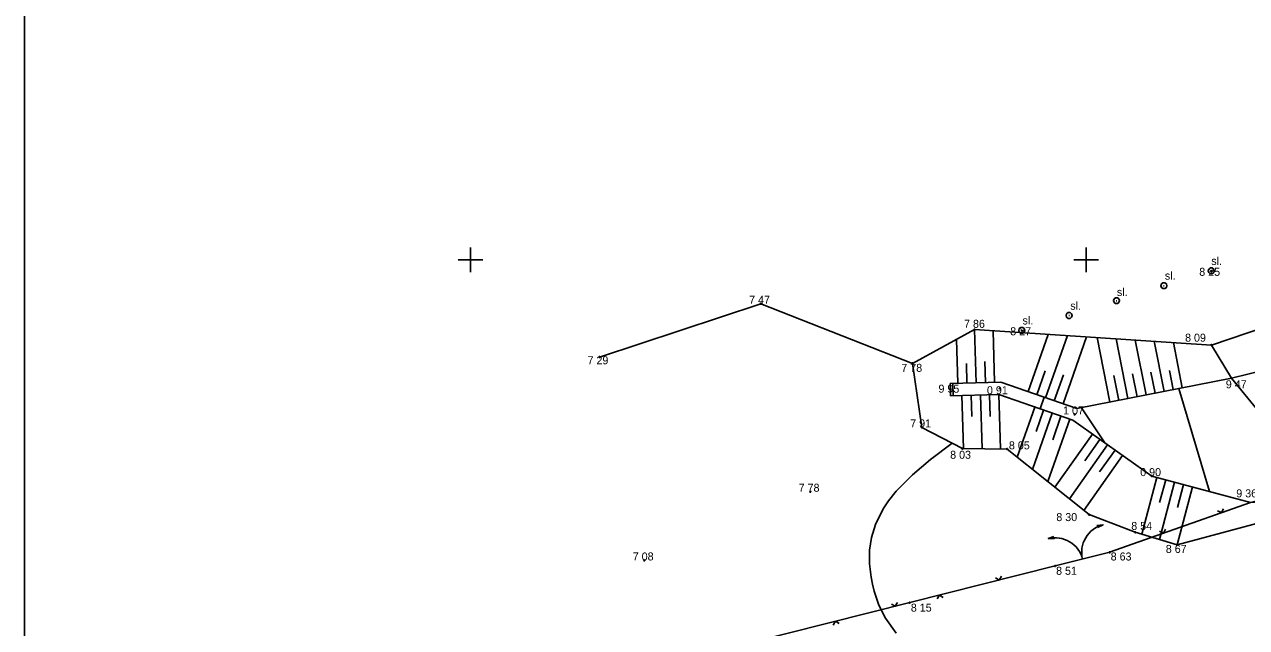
# Model space of a CAD drawing. Extents: x -684336 to -684039, y -993109 to -992688.
# Drawn here: x -684336.2 to -684237, y -992829.9 to -992780.9 of the extents above; entities that cross this region are included whole.
import ezdxf

# ---------------------------------------------------------------- set-up
doc = ezdxf.new("R2010")
doc.units = 0
for name, color, linetype in [('51', 7, 'Continuous'), ('53', 7, 'Continuous'), ('55', 7, 'Continuous'), ('56', 7, 'Continuous'), ('57', 7, 'Continuous'), ('60', 7, 'Continuous'), ('70', 7, 'Continuous'), ('81', 7, 'Continuous')]:
    doc.layers.add(name, color=color, linetype=linetype)

msp = doc.modelspace()

# ---------------------------------------------------------------- linework, layer by layer
at = {"layer": '51'}
for points in [[(-684155.696, -992787.999), (-684158.08, -992789.98), (-684161.21, -992793.24), (-684163.83, -992796.06), (-684166.91, -992797.89), (-684183.05, -992802.89), (-684200, -992808.38), (-684218.61, -992814.31), (-684231.09, -992818.35), (-684236.66, -992819.71), (-684248.11, -992823.77)], [(-684161.21, -992793.24), (-684163.51, -992789.57), (-684179.03, -992792.54), (-684203.02, -992799.48), (-684222.3, -992805.72), (-684238.2, -992809.62), (-684250.775, -992812.098)], [(-684251.105, -992813.042), (-684244.68, -992817.58), (-684236.66, -992819.71), (-684231.37, -992819.36), (-684210.59, -992812.91), (-684194.44, -992808.31), (-684190.16, -992807.38), (-684180.44, -992804.41), (-684173.82, -992803.72), (-684160.95, -992797.464)], [(-684216.49, -992799), (-684239.84, -992806.93), (-684259.07, -992805.67), (-684264.11, -992808.42), (-684263.35, -992813.62), (-684260.06, -992815.34), (-684256.43, -992815.38), (-684249.77, -992820.71), (-684246.02, -992822.14), (-684242.63, -992823.16), (-684230.34, -992819.85)], [(-684250.775, -992812.098), (-684256.942, -992809.937), (-684261.055, -992810.06)], [(-684261.025, -992811.06), (-684261.055, -992810.06)], [(-684251.105, -992813.042), (-684257.098, -992810.943), (-684261.025, -992811.06)], [(-684238.864, -992820.226), (-684239.016, -992820.545), (-684239.335, -992820.393)], [(-684243.577, -992821.897), (-684243.729, -992822.216), (-684244.048, -992822.064)], [(-684227.21, -992890.21), (-684237.13, -992893.77), (-684248.6, -992898.04), (-684263.09, -992903.1), (-684268.1, -992883.39), (-684271.29, -992870.41), (-684274.7, -992857.04), (-684277.74, -992844.67), (-684280.1, -992835.85), (-684277.64, -992831.2), (-684264.34, -992827.86), (-684252.53, -992824.88)], [(-684257.372, -992825.844), (-684257.068, -992826.025), (-684256.887, -992825.721)], [(-684261.612, -992827.43), (-684261.916, -992827.248), (-684262.097, -992827.552)], [(-684265.82, -992827.974), (-684265.516, -992828.155), (-684265.335, -992827.852)], [(-684270.063, -992829.555), (-684270.366, -992829.373), (-684270.547, -992829.677)]]:
    msp.add_lwpolyline(points, dxfattribs=at)
at = {"layer": '53'}
msp.add_lwpolyline([(-684336.213, -993108.726), (-684039.213, -993108.726), (-684039.213, -992688.226), (-684336.213, -992688.226)], close=True, dxfattribs=at)
for points in [[(-684300, -992799), (-684300, -992801)], [(-684250, -992799), (-684250, -992801)], [(-684301, -992800), (-684299, -992800)], [(-684251, -992800), (-684249, -992800)]]:
    msp.add_lwpolyline(points, dxfattribs=at)
at = {"layer": '55'}
for points in [[(-684239.78, -992800.67), (-684239.655, -992800.76), (-684239.605, -992800.905), (-684239.655, -992801.05), (-684239.78, -992801.14), (-684239.935, -992801.14), (-684240.06, -992801.05), (-684240.11, -992800.905), (-684240.06, -992800.76), (-684239.935, -992800.67)], [(-684243.625, -992801.88), (-684243.5, -992801.97), (-684243.45, -992802.115), (-684243.5, -992802.26), (-684243.625, -992802.35), (-684243.78, -992802.35), (-684243.905, -992802.26), (-684243.955, -992802.115), (-684243.905, -992801.97), (-684243.78, -992801.88)], [(-684247.47, -992803.09), (-684247.345, -992803.18), (-684247.295, -992803.325), (-684247.345, -992803.47), (-684247.47, -992803.56), (-684247.625, -992803.56), (-684247.75, -992803.47), (-684247.8, -992803.325), (-684247.75, -992803.18), (-684247.625, -992803.09)], [(-684251.315, -992804.3), (-684251.19, -992804.39), (-684251.14, -992804.535), (-684251.19, -992804.68), (-684251.315, -992804.77), (-684251.47, -992804.77), (-684251.595, -992804.68), (-684251.645, -992804.535), (-684251.595, -992804.39), (-684251.47, -992804.3)], [(-684255.16, -992805.51), (-684255.035, -992805.6), (-684254.985, -992805.745), (-684255.035, -992805.89), (-684255.16, -992805.98), (-684255.315, -992805.98), (-684255.44, -992805.89), (-684255.49, -992805.745), (-684255.44, -992805.6), (-684255.315, -992805.51)]]:
    msp.add_lwpolyline(points, close=True, dxfattribs=at)
for points in [[(-684239.885, -992800.91), (-684239.83, -992800.91)], [(-684243.73, -992802.12), (-684243.675, -992802.12)], [(-684247.575, -992803.33), (-684247.52, -992803.33)], [(-684251.42, -992804.54), (-684251.365, -992804.54)], [(-684255.265, -992805.75), (-684255.21, -992805.75)], [(-684249.08, -992821.766), (-684248.638, -992821.532), (-684249.133, -992821.6)], [(-684252.623, -992822.479), (-684253.091, -992822.654), (-684252.591, -992822.65)], [(-684252.53, -992824.88), (-684248.078, -992823.759)]]:
    msp.add_lwpolyline(points, dxfattribs=at)
for centre, start, end in [((-684248.078, -992823.759), 104.12602, 194.13769), ((-684252.53, -992824.88), 14.13769, 104.14936)]:
    msp.add_arc(centre, 2.296, start, end, dxfattribs=at)
at = {"layer": '57'}
for points in [[(-684239.838, -992800.873), (-684239.815, -992800.91), (-684239.838, -992800.948), (-684239.883, -992800.948), (-684239.905, -992800.91), (-684239.883, -992800.873)], [(-684276.407, -992803.542), (-684276.385, -992803.58), (-684276.407, -992803.617), (-684276.453, -992803.617), (-684276.475, -992803.58), (-684276.453, -992803.542)], [(-684259.047, -992805.633), (-684259.025, -992805.67), (-684259.047, -992805.708), (-684259.093, -992805.708), (-684259.115, -992805.67), (-684259.093, -992805.633)], [(-684255.218, -992805.713), (-684255.195, -992805.75), (-684255.218, -992805.787), (-684255.263, -992805.787), (-684255.285, -992805.75), (-684255.263, -992805.713)], [(-684239.818, -992806.893), (-684239.795, -992806.93), (-684239.818, -992806.968), (-684239.863, -992806.968), (-684239.885, -992806.93), (-684239.863, -992806.893)], [(-684289.498, -992807.873), (-684289.475, -992807.91), (-684289.498, -992807.948), (-684289.542, -992807.948), (-684289.565, -992807.91), (-684289.542, -992807.873)], [(-684264.088, -992808.383), (-684264.065, -992808.42), (-684264.088, -992808.458), (-684264.133, -992808.458), (-684264.155, -992808.42), (-684264.133, -992808.383)], [(-684261.018, -992810.523), (-684260.995, -992810.56), (-684261.018, -992810.598), (-684261.062, -992810.598), (-684261.085, -992810.56), (-684261.062, -992810.523)], [(-684256.998, -992810.402), (-684256.975, -992810.44), (-684256.998, -992810.477), (-684257.042, -992810.477), (-684257.065, -992810.44), (-684257.042, -992810.402)], [(-684238.177, -992809.583), (-684238.155, -992809.62), (-684238.177, -992809.657), (-684238.222, -992809.657), (-684238.245, -992809.62), (-684238.222, -992809.583)], [(-684250.917, -992812.532), (-684250.895, -992812.57), (-684250.917, -992812.607), (-684250.962, -992812.607), (-684250.985, -992812.57), (-684250.962, -992812.532)], [(-684263.327, -992813.583), (-684263.305, -992813.62), (-684263.327, -992813.657), (-684263.372, -992813.657), (-684263.395, -992813.62), (-684263.372, -992813.583)], [(-684260.038, -992815.302), (-684260.015, -992815.34), (-684260.038, -992815.378), (-684260.083, -992815.378), (-684260.105, -992815.34), (-684260.083, -992815.302)], [(-684256.407, -992815.343), (-684256.385, -992815.38), (-684256.407, -992815.417), (-684256.453, -992815.417), (-684256.475, -992815.38), (-684256.453, -992815.343)], [(-684244.657, -992817.542), (-684244.635, -992817.58), (-684244.657, -992817.617), (-684244.703, -992817.617), (-684244.725, -992817.58), (-684244.703, -992817.542)], [(-684272.388, -992818.812), (-684272.365, -992818.85), (-684272.388, -992818.888), (-684272.432, -992818.888), (-684272.455, -992818.85), (-684272.432, -992818.812)], [(-684249.748, -992820.672), (-684249.725, -992820.71), (-684249.748, -992820.747), (-684249.792, -992820.747), (-684249.815, -992820.71), (-684249.792, -992820.672)], [(-684245.998, -992822.103), (-684245.975, -992822.14), (-684245.998, -992822.177), (-684246.042, -992822.177), (-684246.065, -992822.14), (-684246.042, -992822.103)], [(-684242.608, -992823.123), (-684242.585, -992823.16), (-684242.608, -992823.198), (-684242.653, -992823.198), (-684242.675, -992823.16), (-684242.653, -992823.123)], [(-684285.858, -992824.393), (-684285.835, -992824.43), (-684285.858, -992824.468), (-684285.903, -992824.468), (-684285.925, -992824.43), (-684285.903, -992824.393)], [(-684248.088, -992823.733), (-684248.065, -992823.77), (-684248.088, -992823.807), (-684248.133, -992823.807), (-684248.155, -992823.77), (-684248.133, -992823.733)], [(-684252.508, -992824.843), (-684252.485, -992824.88), (-684252.508, -992824.917), (-684252.552, -992824.917), (-684252.575, -992824.88), (-684252.552, -992824.843)], [(-684264.318, -992827.823), (-684264.295, -992827.86), (-684264.318, -992827.897), (-684264.363, -992827.897), (-684264.385, -992827.86), (-684264.363, -992827.823)]]:
    msp.add_lwpolyline(points, close=True, dxfattribs=at)
at = {"layer": '60'}
msp.add_lwpolyline([(-684289.52, -992807.91), (-684276.43, -992803.58), (-684264.11, -992808.42), (-684259.07, -992805.67), (-684239.84, -992806.93), (-684238.2, -992809.62), (-684231.09, -992818.35), (-684218.61, -992814.31), (-684200, -992808.38), (-684183.05, -992802.89), (-684179.03, -992792.54), (-684175.03, -992780.95)], dxfattribs=at)
at = {"layer": '70'}
for points in [[(-684260.44, -992810.042), (-684260.547, -992806.476)], [(-684258.941, -992809.997), (-684259.07, -992805.67)], [(-684258.941, -992809.997), (-684259.07, -992805.67)], [(-684257.442, -992809.952), (-684257.566, -992805.769)], [(-684254.719, -992810.716), (-684253.089, -992806.062)], [(-684253.304, -992811.212), (-684251.535, -992806.164)], [(-684251.888, -992811.708), (-684249.981, -992806.266)], [(-684248.091, -992811.569), (-684249.125, -992806.322)], [(-684246.619, -992811.279), (-684247.576, -992806.423)], [(-684245.148, -992810.989), (-684246.027, -992806.525)], [(-684243.676, -992810.699), (-684244.479, -992806.626)], [(-684242.204, -992810.409), (-684242.93, -992806.728)], [(-684259.69, -992810.019), (-684259.738, -992808.441)], [(-684258.191, -992809.975), (-684258.242, -992808.273)], [(-684254.011, -992810.964), (-684253.332, -992809.024)], [(-684252.596, -992811.46), (-684251.861, -992809.362)], [(-684247.355, -992811.424), (-684247.753, -992809.403)], [(-684245.883, -992811.134), (-684246.251, -992809.27)], [(-684244.412, -992810.844), (-684244.748, -992809.137)], [(-684242.94, -992810.554), (-684243.246, -992809.003)], [(-684260.096, -992811.032), (-684259.968, -992815.341)], [(-684259.347, -992811.01), (-684259.295, -992812.746)], [(-684258.597, -992810.987), (-684258.467, -992815.358)], [(-684257.847, -992810.965), (-684257.795, -992812.725)], [(-684257.098, -992810.943), (-684256.965, -992815.374)], [(-684254.178, -992811.966), (-684255.605, -992816.04)], [(-684252.762, -992812.462), (-684254.364, -992817.034)], [(-684253.47, -992812.214), (-684254.076, -992813.943)], [(-684251.346, -992812.957), (-684253.122, -992818.027)], [(-684252.054, -992812.709), (-684252.73, -992814.638)], [(-684249.504, -992814.173), (-684252.55, -992818.485)], [(-684248.279, -992815.038), (-684251.377, -992819.424)], [(-684248.892, -992814.605), (-684250.12, -992816.345)], [(-684247.667, -992815.471), (-684248.916, -992817.24)], [(-684247.054, -992815.903), (-684250.204, -992820.363)], [(-684244.28, -992817.686), (-684245.504, -992822.295)], [(-684242.83, -992818.071), (-684244.067, -992822.728)], [(-684243.555, -992817.879), (-684244.048, -992819.732)], [(-684241.381, -992818.456), (-684242.63, -992823.16)], [(-684242.106, -992818.264), (-684242.603, -992820.136)]]:
    msp.add_lwpolyline(points, dxfattribs=at)
at = {"layer": '81'}
for points in [[(-684260.822, -992811.054), (-684260.847, -992810.054)], [(-684239.993, -992818.825), (-684242.479, -992810.463)], [(-684253.757, -992812.113), (-684253.432, -992811.167)], [(-684248.506, -992814.878), (-684250.377, -992812.02)], [(-684265.442, -992830.348), (-684266.311, -992829.115), (-684266.66, -992828.443), (-684266.862, -992827.974), (-684267.217, -992826.922), (-684267.358, -992826.362), (-684267.47, -992825.793), (-684267.596, -992824.704), (-684267.612, -992824.207), (-684267.589, -992823.588), (-684267.439, -992822.56), (-684267.121, -992821.504), (-684266.5, -992820.243), (-684266.068, -992819.592), (-684265.445, -992818.81), (-684264.107, -992817.463), (-684262.64, -992816.239), (-684260.883, -992814.91)]]:
    msp.add_lwpolyline(points, dxfattribs=at)

# ---------------------------------------------------------------- texts
at = {"layer": '56'}
for p in [(-684239.852, -992800.426), (-684243.623, -992801.621), (-684247.515, -992802.95), (-684251.3, -992804.065), (-684255.178, -992805.26)]:
    msp.add_text('sl.', height=0.65, dxfattribs=at).set_placement(p)
at = {"layer": '57'}
for s, p in [('8 25', (-684240.828, -992801.308)), ('7 47', (-684277.374, -992803.58)), ('7 86', (-684259.925, -992805.532)), ('8 27', (-684256.178, -992806.136)), ('8 09', (-684241.98, -992806.659)), ('7 29', (-684290.497, -992808.495)), ('7 78', (-684265.018, -992809.11)), ('9 95', (-684262.003, -992810.803)), ('0 91', (-684258.067, -992810.928)), ('9 47', (-684238.673, -992810.445)), ('1 07', (-684251.884, -992812.57)), ('7 91', (-684264.294, -992813.62)), ('8 05', (-684256.284, -992815.408)), ('8 03', (-684261.054, -992816.17)), ('0 90', (-684245.624, -992817.58)), ('7 78', (-684273.354, -992818.85)), ('9 36', (-684237.823, -992819.305)), ('8 30', (-684252.433, -992821.234)), ('8 54', (-684246.35, -992821.95)), ('8 67', (-684243.546, -992823.82)), ('7 08', (-684286.824, -992824.43)), ('8 63', (-684248.02, -992824.434)), ('8 51', (-684252.453, -992825.596)), ('8 15', (-684264.246, -992828.589))]:
    msp.add_text(s, height=0.65, dxfattribs=at).set_placement(p)

doc.saveas('drawing.dxf')
